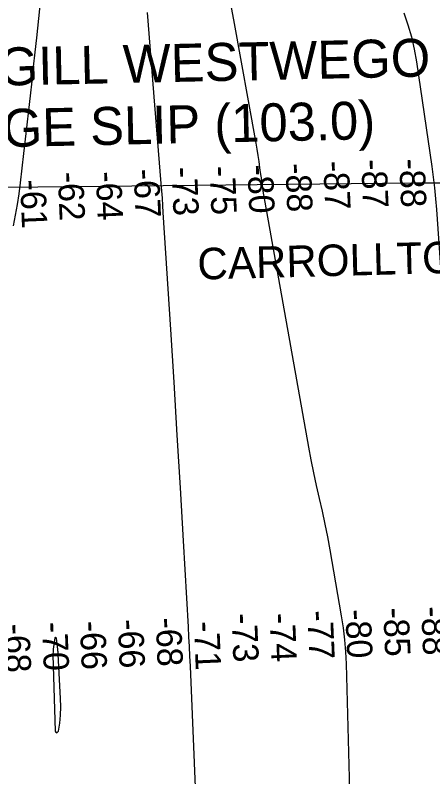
# Model space of a CAD drawing. Extents: x 3651524 to 3689615, y 505651 to 531377.
# Drawn here: x 3658467 to 3659567, y 521661 to 523666 of the extents above; entities that cross this region are included whole.
import ezdxf

# ---------------------------------------------------------------- set-up
doc = ezdxf.new("R2010")
doc.units = 0
for name, color, linetype in [('V-CHAN-NAID', 7, 'Continuous'), ('V-GRID-MAJR', 7, 'Continuous'), ('V-RIVR-GAGE-IDEN', 7, 'Continuous'), ('V-RIVR-RANG', 7, 'Continuous'), ('V-TOPO-MINR', 7, 'Continuous')]:
    doc.layers.add(name, color=color, linetype=linetype)

msp = doc.modelspace()

# ---------------------------------------------------------------- linework, layer by layer
at = {"layer": 'V-GRID-MAJR'}
msp.add_spline([(3655639.78, 523183.706), (3660918.553, 523238.605), (3666197.317, 523294.271), (3671476.073, 523350.705), (3676754.821, 523407.907), (3682033.561, 523465.877), (3687312.292, 523524.615)], degree=3, dxfattribs=at)
at = {"layer": 'V-TOPO-MINR'}
for points in [[(3659026.93, 523733.516), (3659042.145, 523653.804), (3659100.177, 523328.658), (3659102.959, 523312.571), (3659105.628, 523296.466), (3659108.124, 523280.334), (3659110.506, 523264.183), (3659112.348, 523251.219), (3659113.73, 523241.537), (3659115.121, 523231.858), (3659116.526, 523222.18), (3659117.941, 523212.504), (3659119.406, 523202.836), (3659120.93, 523193.177), (3659122.543, 523183.533), (3659124.215, 523173.898), (3659239.181, 522528.989), (3659245.558, 522495.011), (3659252.347, 522461.119), (3659259.752, 522427.357), (3659267.568, 522393.681), (3659275.359, 522360), (3659282.704, 522326.228), (3659289.382, 522292.317), (3659295.615, 522258.314), (3659325.747, 522084.28), (3659330.487, 522052.858), (3659334.314, 522021.346), (3659336.77, 521989.696), (3659338.313, 521957.957), (3659362.489, 521058.531)], [(3658533.267, 523708.982), (3658522.559, 523606.039), (3658518.532, 523567.914), (3658514.424, 523529.797), (3658510.195, 523491.694), (3658505.885, 523453.599), (3658501.513, 523415.512), (3658497.14, 523377.424), (3658492.764, 523339.337), (3658488.387, 523301.25), (3658479.531, 523224.207), (3658475.894, 523195.814), (3658471.768, 523167.5), (3658466.908, 523139.302), (3658461.56, 523111.181)], [(3658814.576, 523672.948), (3658824.086, 523550.724), (3658833.819, 523428.516), (3658850.526, 523222.293), (3658852.022, 523203.206), (3658853.451, 523184.115), (3658854.781, 523165.016), (3658856.043, 523145.912), (3658875.56, 522838.458), (3658884.259, 522699.394), (3658892.787, 522560.32), (3658901.06, 522421.231), (3658909.162, 522282.131), (3658922.15, 522055.574), (3658923.569, 522029.742), (3658924.907, 522003.905), (3658926.122, 521978.063), (3658927.256, 521952.217), (3658968.633, 520955.227)], [(3659490.687, 523672.21), (3659501.281, 523640.502), (3659510.522, 523608.449), (3659517.735, 523575.88), (3659523.595, 523542.966), (3659563.728, 523267.686), (3659567.543, 523239.389), (3659570.951, 523211.048), (3659573.749, 523182.64), (3659576.14, 523154.188), (3659586.374, 523014.385), (3659592.969, 522915.966), (3659598.754, 522817.504), (3659603.324, 522718.979), (3659607.084, 522620.411), (3659624.186, 522085.419), (3659624.855, 522058.883), (3659625.285, 522032.345), (3659625.357, 522005.803), (3659625.19, 521979.259), (3659622.526, 521775.165), (3659619.966, 521646.604)], [(3658576.142, 521777.007), (3658578.478, 521778.051), (3658580.937, 521780.712), (3658584.05, 521802.092), (3658586.16, 521823.536), (3658586.766, 521845.075), (3658586.37, 521866.676), (3658580.115, 521983.775), (3658579.917, 521986.839), (3658579.674, 521989.898), (3658579.363, 521992.952), (3658579.006, 521996.001), (3658575.212, 522025.598), (3658574.611, 522027.073), (3658574.049, 522027.613), (3658573.357, 522028.055), (3658572.705, 522028.116), (3658572.156, 522027.991), (3658571.764, 522027.588), (3658571.475, 522026.999), (3658567.131, 521996.886), (3658566.685, 521993.113), (3658566.37, 521989.332), (3658566.25, 521985.54), (3658566.26, 521981.741), (3658571.959, 521781.392), (3658573.989, 521778.391), (3658576.142, 521777.007)]]:
    msp.add_lwpolyline(points, dxfattribs=at)

# ---------------------------------------------------------------- texts
at = {"layer": 'V-CHAN-NAID'}
for s, p in [('CARGILL WESTWEGO', (3658142.086, 523473.824)), ('BARGE SLIP (103.0)', (3658159.99, 523312.361))]:
    msp.add_text(s, height=100, rotation=1.24031, dxfattribs=at).set_placement(p)
at = {"layer": 'V-RIVR-GAGE-IDEN'}
msp.add_text('CARROLLTON GAGE', height=83, rotation=1.52077, dxfattribs=at).set_placement((3658947.75, 522969.509))
at = {"layer": 'V-RIVR-RANG'}
for s, rotation, p in [('-87', 272.426694, (3659278.101, 523281.451)), ('-87', 272.426694, (3659378.021, 523285.438)), ('-88', 272.426694, (3659478.031, 523287.317)), ('-67', 272.426694, (3658778.542, 523260.462)), ('-73', 272.426694, (3658878.419, 523265.503)), ('-75', 272.426694, (3658978.406, 523267.909)), ('-80', 272.426694, (3659078.338, 523271.633)), ('-88', 272.426694, (3659178.269, 523275.356)), ('-62', 272.426694, (3658578.701, 523252.487)), ('-64', 272.426694, (3658678.745, 523253.575)), ('-61', 272.426694, (3658479.485, 523231.897)), ('-77', 272.465167, (3659236.104, 522098.028)), ('-80', 272.465167, (3659336.079, 522100.764)), ('-85', 272.465167, (3659435.962, 522105.608)), ('-88', 272.465167, (3659535.925, 522108.608)), ('-68', 272.465167, (3658836.547, 522079.175)), ('-73', 272.465167, (3659036.245, 522090.446)), ('-74', 272.465167, (3659136.311, 522091.075)), ('-68', 272.465167, (3658436.876, 522062.958)), ('-70', 272.465167, (3658536.759, 522067.804)), ('-66', 272.465167, (3658636.733, 522070.54)), ('-66', 272.465167, (3658736.651, 522074.594)), ('-71', 272.465167, (3658937.065, 522069.262))]:
    msp.add_text(s, height=67, rotation=rotation, dxfattribs=at).set_placement(p)

doc.saveas('drawing.dxf')
